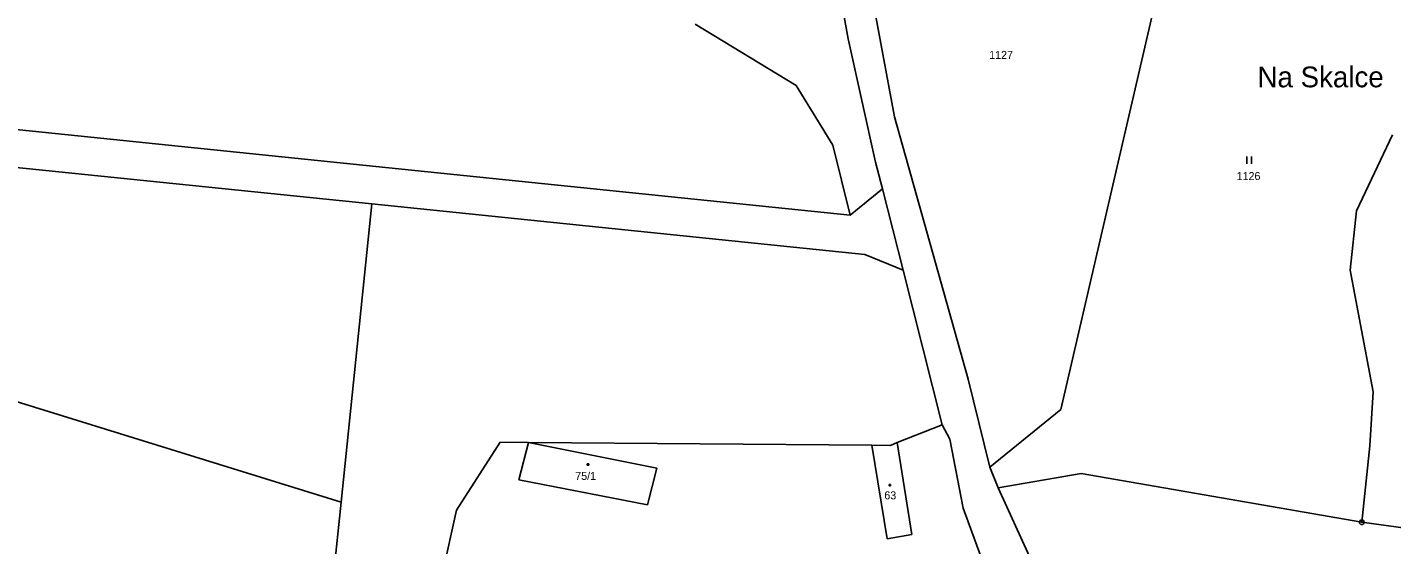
# Model space of a CAD drawing. Extents: x -796130 to -793145, y -1109506 to -1106267.
# Drawn here: x -794609.3 to -794319.4, y -1108157.6 to -1108047.8 of the extents above; entities that cross this region are included whole.
import ezdxf

# ---------------------------------------------------------------- set-up
doc = ezdxf.new("R2010")
doc.units = 0
for name, color, linetype in [('Vrstva 1', 7, 'Continuous'), ('Vrstva 14', 7, 'Continuous'), ('Vrstva 15', 7, 'Continuous'), ('Vrstva 23', 7, 'Continuous'), ('Vrstva 25', 7, 'Continuous'), ('Vrstva 28', 7, 'Continuous'), ('Vrstva 39', 7, 'Continuous')]:
    doc.layers.add(name, color=color, linetype=linetype)

msp = doc.modelspace()

# ---------------------------------------------------------------- linework, layer by layer
at = {"layer": 'Vrstva 1'}
for p, q in [((-794361.62, -1108007.82), (-794389.73, -1108128.9)), ((-794425.07, -1108066.76), (-794433.02, -1108024.01)), ((-794438.45, -1108030.86), (-794434.88, -1108050.22)), ((-794445.93, -1108060.11), (-794467.4, -1108047.08)), ((-794434.88, -1108050.22), (-794429.08, -1108076.44)), ((-794438.15, -1108072.8), (-794445.93, -1108060.11)), ((-794535.24, -1108077.32), (-794653.33, -1108065.2)), ((-794409.41, -1108122.5), (-794425.07, -1108066.76)), ((-794683.27, -1108070.18), (-794536.14, -1108085.28)), ((-794319.23, -1108070.58), (-794326.93, -1108086.75)), ((-794434.49, -1108087.66), (-794438.15, -1108072.8)), ((-794429.08, -1108076.44), (-794427.65, -1108082.08)), ((-794434.49, -1108087.66), (-794535.24, -1108077.32)), ((-794434.49, -1108087.66), (-794427.65, -1108082.08)), ((-794427.65, -1108082.08), (-794423.26, -1108099.33)), ((-794536.14, -1108085.28), (-794542.64, -1108148.6)), ((-794536.14, -1108085.28), (-794431.36, -1108096.04)), ((-794326.93, -1108086.75), (-794328.25, -1108099.33)), ((-794431.36, -1108096.04), (-794423.26, -1108099.33)), ((-794423.26, -1108099.33), (-794414.92, -1108132.19)), ((-794328.25, -1108099.33), (-794323.35, -1108125.15)), ((-794695.01, -1108101.53), (-794542.64, -1108148.6)), ((-794409.41, -1108122.5), (-794406, -1108136.31)), ((-794323.35, -1108125.15), (-794324.05, -1108136.66)), ((-794404.79, -1108141.21), (-794389.73, -1108128.9)), ((-794414.92, -1108132.19), (-794424.47, -1108135.96)), ((-794413.32, -1108135.21), (-794414.92, -1108132.19)), ((-794518.13, -1108150.32), (-794508.85, -1108135.87)), ((-794508.85, -1108135.87), (-794502.81, -1108135.92)), ((-794502.81, -1108135.92), (-794504.87, -1108143.89)), ((-794475.56, -1108141.36), (-794502.81, -1108135.92)), ((-794502.81, -1108135.92), (-794429.91, -1108136.51)), ((-794429.91, -1108136.51), (-794425.93, -1108136.54)), ((-794429.91, -1108136.51), (-794426.6, -1108156.42)), ((-794424.47, -1108135.96), (-794425.93, -1108136.54)), ((-794421.4, -1108155.51), (-794424.47, -1108135.96)), ((-794410.51, -1108149.9), (-794413.32, -1108135.21)), ((-794406, -1108136.31), (-794404.79, -1108141.21)), ((-794324.05, -1108136.66), (-794325.8, -1108152.88)), ((-794477.56, -1108149.15), (-794475.56, -1108141.36)), ((-794403.02, -1108145.53), (-794404.79, -1108141.21)), ((-794385.38, -1108142.55), (-794403.02, -1108145.53)), ((-794325.8, -1108152.88), (-794385.38, -1108142.55)), ((-794504.87, -1108143.89), (-794477.56, -1108149.15)), ((-794396.36, -1108160.15), (-794403.02, -1108145.53)), ((-794542.64, -1108148.6), (-794555, -1108269.12)), ((-794521.17, -1108164.02), (-794518.13, -1108150.32)), ((-794402.21, -1108172.39), (-794410.51, -1108149.9)), ((-794325.8, -1108152.88), (-794282.07, -1108158.86)), ((-794426.6, -1108156.42), (-794421.4, -1108155.51))]:
    msp.add_line(p, q, dxfattribs=at)
at = {"layer": 'Vrstva 23'}
for p, q in [((-794350.22, -1108076.74), (-794350.22, -1108075.24)), ((-794349.22, -1108075.24), (-794349.22, -1108076.74))]:
    msp.add_line(p, q, dxfattribs=at)
at = {"layer": 'Vrstva 25'}
for p, q in [((-794490.34, -1108140.44), (-794490.04, -1108140.44)), ((-794490.34, -1108140.74), (-794490.34, -1108140.44)), ((-794490.04, -1108140.44), (-794490.04, -1108140.74)), ((-794490.04, -1108140.74), (-794490.34, -1108140.74)), ((-794426.21, -1108144.83), (-794425.91, -1108144.83)), ((-794426.21, -1108145.13), (-794426.21, -1108144.83)), ((-794425.91, -1108145.13), (-794426.21, -1108145.13)), ((-794425.91, -1108144.83), (-794425.91, -1108145.13))]:
    msp.add_line(p, q, dxfattribs=at)
at = {"layer": 'Vrstva 28'}
for radius in [0.5, 0.01]:
    msp.add_circle((-794325.8, -1108152.88), radius, dxfattribs=at)

# ---------------------------------------------------------------- texts
at = {"layer": 'Vrstva 14'}
for s, p in [('1127', (-794404.949, -1108054.48)), ('1126', (-794352.373, -1108080.21))]:
    msp.add_text(s, height=1.7, dxfattribs=at).set_placement(p)
at = {"layer": 'Vrstva 15'}
for s, p in [('75/1', (-794492.906, -1108143.89)), ('63', (-794427.227, -1108148.01))]:
    msp.add_text(s, height=1.7, dxfattribs=at).set_placement(p)
at = {"layer": 'Vrstva 39'}
msp.add_text('Na Skalce', height=4.4, dxfattribs=at).set_placement((-794347.94, -1108060.51))

doc.saveas('drawing.dxf')
